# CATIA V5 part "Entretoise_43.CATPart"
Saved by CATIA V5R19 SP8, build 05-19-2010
Part number: Entretoise_43_gauche
Bounding box of the stored display mesh (mm): x -19 to 19, y -18.807 to 18.807, z 0 to 51
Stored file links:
  G:\EU_thinkMotion\CFAO_2010\MMS_groupe1\MMS_groupe1\OK\vduret\vduret\CATIA\Entretoise_43.CATPart
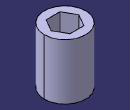
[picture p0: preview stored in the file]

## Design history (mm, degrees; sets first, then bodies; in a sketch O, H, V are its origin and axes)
Body1 (main body)
  Sketch1 on xy-plane, origin (0, 0, 0), H (1, 0, 0), V (0, 1, 0)
    circle A1 centre (0, 0) radius 19
    point P1 (0, 0)
    point P2 (6.3509, -11)
    point P3 (12.7017, 0)
    point P4 (6.3509, 11)
    point P5 (-6.3509, 11)
    point P6 (-12.7017, 0)
    point P7 (-6.3509, -11)
    point P8 (9.5263, -5.5)
    line L1 (6.3509, -11) -> (12.7017, 0)
    line L2 (12.7017, 0) -> (6.3509, 11)
    line L3 (6.3509, 11) -> (-6.3509, 11)
    line L4 (-6.3509, 11) -> (-12.7017, 0)
    line L5 (-12.7017, 0) -> (-6.3509, -11)
    line L6 (-6.3509, -11) -> (6.3509, -11)
    construction line L7 (0, 0) -> (9.5263, -5.5)
    construction circle A2 centre (0, 0) radius 12.7017
    construction arc A3 centre (-12.7017, 0) radius 12.7017 from (-6.3509, 11) to (-6.3509, -11) cw
    construction arc A4 centre (12.7017, 0) radius 12.7017 from (6.3509, 11) to (6.3509, -11) ccw
    radius A1 = 19
    distance L3 L6 = 22
    coincidence: A2 P2, A2 P3, A2 P4, A2 P5, A2 P6, A2 P7, A3 P1, A4 P1, P1 O
    midpoint: P8 L1
    parallelism: L1 L4
    horizontal: L3 H
  Pad1: profile Sketch1, direction (0, 0, 1), length 51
